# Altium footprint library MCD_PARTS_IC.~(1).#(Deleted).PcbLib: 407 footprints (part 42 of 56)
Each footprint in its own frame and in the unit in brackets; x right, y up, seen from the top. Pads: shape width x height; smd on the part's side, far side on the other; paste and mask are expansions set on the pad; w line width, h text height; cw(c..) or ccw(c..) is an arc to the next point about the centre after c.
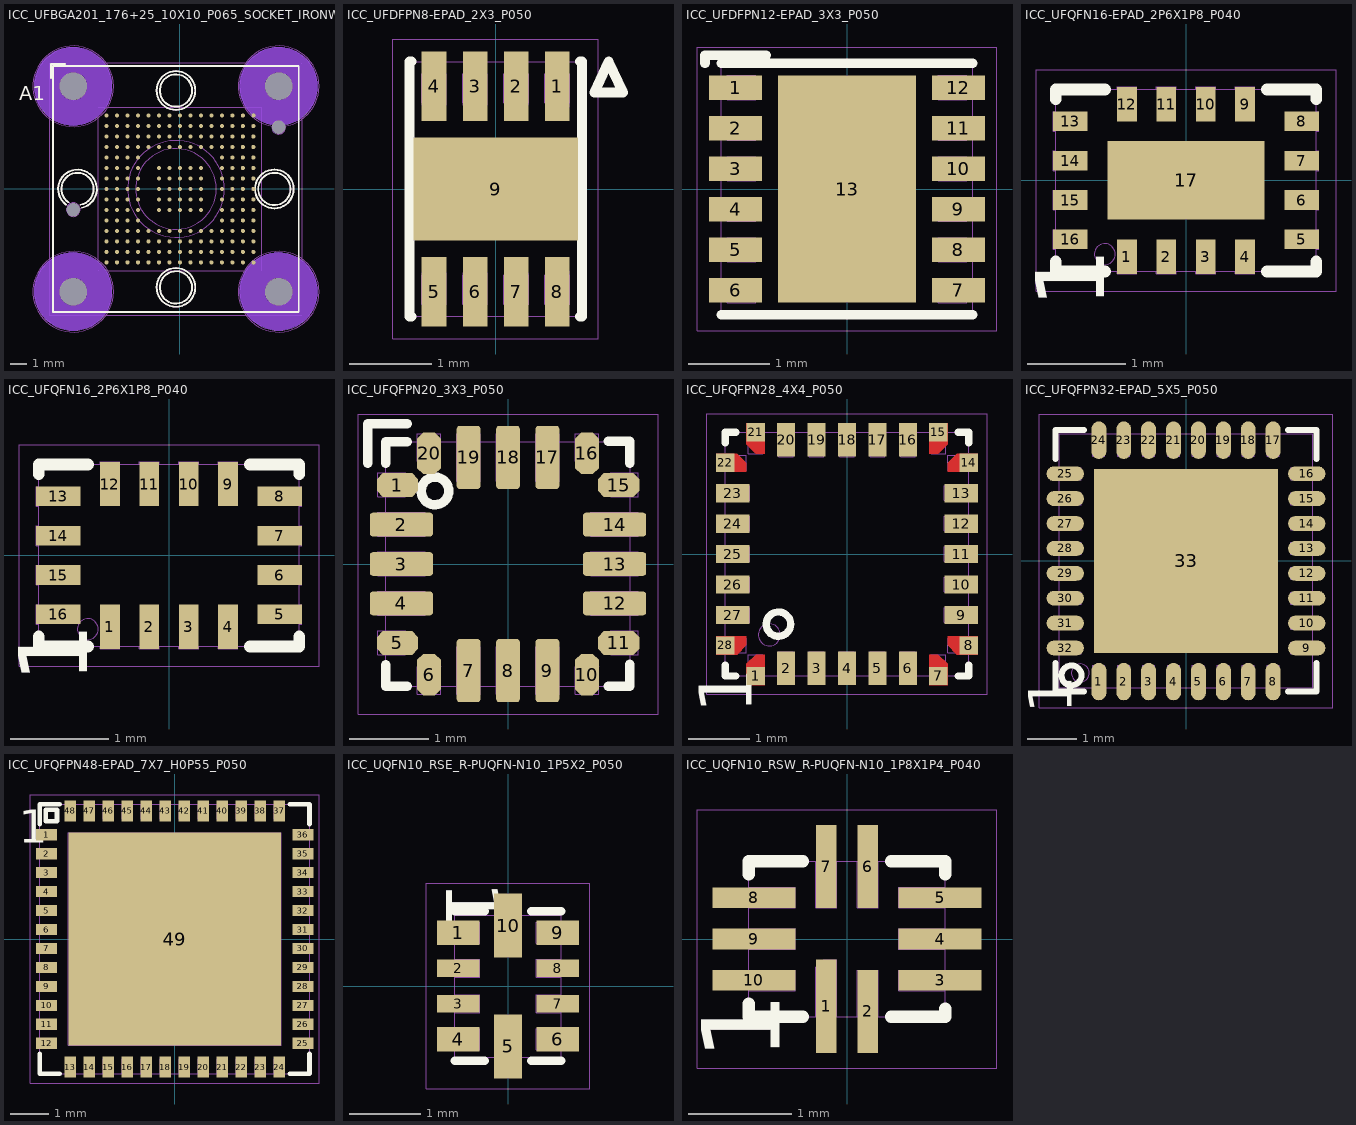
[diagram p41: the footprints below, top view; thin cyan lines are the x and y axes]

## ICC_UFBGA201_176+25_10X10_P065_SOCKET_IRONWOOD_C23913 [mm] "MCD-04409"
height 9.88
pads (207):
  round 0 hole 1.7 unplated mask+0.05: 0(-6.612,-6.368) 0(-6.612,6.362) 0(6.118,-6.368) 0(6.118,6.362)
  round 0 hole 0.85 unplated mask+0.05: 0(-6.612,-1.282) 0(6.118,3.822)
  round 0.25 smd mask+0.038: A1(-4.55,4.55) A2(-3.9,4.55) A3(-3.25,4.55) A4(-2.6,4.55) A5(-1.95,4.55) A6(-1.3,4.55) A7(-0.65,4.55) A8(0,4.55) A9(0.65,4.55) A10(1.3,4.55) A11(1.95,4.55) A12(2.6,4.55) A13(3.25,4.55) A14(3.9,4.55) A15(4.55,4.55) B1(-4.55,3.9) B2(-3.9,3.9) B3(-3.25,3.9) B4(-2.6,3.9) B5(-1.95,3.9) B6(-1.3,3.9) B7(-0.65,3.9) B8(0,3.9) B9(0.65,3.9) B10(1.3,3.9) B11(1.95,3.9) B12(2.6,3.9) B13(3.25,3.9) B14(3.9,3.9) B15(4.55,3.9) C1(-4.55,3.25) C2(-3.9,3.25) C3(-3.25,3.25) C4(-2.6,3.25) C5(-1.95,3.25) C6(-1.3,3.25) C7(-0.65,3.25) C8(0,3.25) C9(0.65,3.25) C10(1.3,3.25) C11(1.95,3.25) C12(2.6,3.25) C13(3.25,3.25) C14(3.9,3.25) C15(4.55,3.25) D1(-4.55,2.6) D2(-3.9,2.6) D3(-3.25,2.6) D4(-2.6,2.6) D5(-1.95,2.6) D6(-1.3,2.6) D7(-0.65,2.6) D8(0,2.6) D9(0.65,2.6) D10(1.3,2.6) D11(1.95,2.6) D12(2.6,2.6) D13(3.25,2.6) D14(3.9,2.6) D15(4.55,2.6) E1(-4.55,1.95) E2(-3.9,1.95) E3(-3.25,1.95) E4(-2.6,1.95) E12(2.6,1.95) E13(3.25,1.95) E14(3.9,1.95) E15(4.55,1.95) F1(-4.55,1.3) F2(-3.9,1.3) F3(-3.25,1.3) F4(-2.6,1.3) F6(-1.3,1.3) F7(-0.65,1.3) F8(0,1.3) F9(0.65,1.3) F10(1.3,1.3) F12(2.6,1.3) F13(3.25,1.3) F14(3.9,1.3) F15(4.55,1.3) G1(-4.55,0.65) G2(-3.9,0.65) G3(-3.25,0.65) G4(-2.6,0.65) G6(-1.3,0.65) G7(-0.65,0.65) G8(0,0.65) G9(0.65,0.65) G10(1.3,0.65) G12(2.6,0.65) G13(3.25,0.65) G14(3.9,0.65) G15(4.55,0.65) H1(-4.55,0) H2(-3.9,0) H3(-3.25,0) H4(-2.6,0) H6(-1.3,0) H7(-0.65,0) H8(0,0) H9(0.65,0) H10(1.3,0) H12(2.6,0) H13(3.25,0) H14(3.9,0) H15(4.55,0) J1(-4.55,-0.65) J2(-3.9,-0.65) J3(-3.25,-0.65) J4(-2.6,-0.65) J6(-1.3,-0.65) J7(-0.65,-0.65) J8(0,-0.65) J9(0.65,-0.65) J10(1.3,-0.65) J12(2.6,-0.65) J13(3.25,-0.65) J14(3.9,-0.65) J15(4.55,-0.65) K1(-4.55,-1.3) K2(-3.9,-1.3) K3(-3.25,-1.3) K4(-2.6,-1.3) K6(-1.3,-1.3) K7(-0.65,-1.3) K8(0,-1.3) K9(0.65,-1.3) K10(1.3,-1.3) K12(2.6,-1.3) K13(3.25,-1.3) K14(3.9,-1.3) K15(4.55,-1.3) L1(-4.55,-1.95) L2(-3.9,-1.95) L3(-3.25,-1.95) L4(-2.6,-1.95) L12(2.6,-1.95) L13(3.25,-1.95) L14(3.9,-1.95) L15(4.55,-1.95) M1(-4.55,-2.6) M2(-3.9,-2.6) M3(-3.25,-2.6) M4(-2.6,-2.6) M5(-1.95,-2.6) M6(-1.3,-2.6) M7(-0.65,-2.6) M8(0,-2.6) M9(0.65,-2.6) M10(1.3,-2.6) M11(1.95,-2.6) M12(2.6,-2.6) M13(3.25,-2.6) M14(3.9,-2.6) M15(4.55,-2.6) N1(-4.55,-3.25) N2(-3.9,-3.25) N3(-3.25,-3.25) N4(-2.6,-3.25) N5(-1.95,-3.25) N6(-1.3,-3.25) N7(-0.65,-3.25) N8(0,-3.25) N9(0.65,-3.25) N10(1.3,-3.25) N11(1.95,-3.25) N12(2.6,-3.25) N13(3.25,-3.25) N14(3.9,-3.25) N15(4.55,-3.25) P1(-4.55,-3.9) P2(-3.9,-3.9) P3(-3.25,-3.9) P4(-2.6,-3.9) P5(-1.95,-3.9) P6(-1.3,-3.9) P7(-0.65,-3.9) P8(0,-3.9) P9(0.65,-3.9) P10(1.3,-3.9) P11(1.95,-3.9) P12(2.6,-3.9) P13(3.25,-3.9) P14(3.9,-3.9) P15(4.55,-3.9) R1(-4.55,-4.55) R2(-3.9,-4.55) R3(-3.25,-4.55) R4(-2.6,-4.55) R5(-1.95,-4.55) R6(-1.3,-4.55) R7(-0.65,-4.55) R8(0,-4.55) R9(0.65,-4.55) R10(1.3,-4.55) R11(1.95,-4.55) R12(2.6,-4.55) R13(3.25,-4.55) R14(3.9,-4.55) R15(4.55,-4.55)
Bottom Layer keep-out:
  region: -4.212,-6.367 -5.75,-6.367 -5.75,-6.355 -5.754,-6.441 -5.788,-6.609 -5.853,-6.767 -5.949,-6.91 -6.07,-7.031 -6.213,-7.127 -6.371,-7.192 -6.539,-7.226 -6.625,-7.23 -6.708,-7.226 -6.872,-7.193 -7.026,-7.13 -7.164,-7.037 -7.282,-6.919 -7.375,-6.781 -7.438,-6.627 -7.471,-6.463 -7.475,-6.38 -7.471,-6.294 -7.437,-6.126 -7.372,-5.968 -7.276,-5.825 -7.155,-5.704 -7.012,-5.608 -6.854,-5.543 -6.686,-5.509 -6.6,-5.505 -6.517,-5.509 -6.353,-5.542 -6.199,-5.605 -6.061,-5.698 -5.943,-5.816 -5.85,-5.954 -5.787,-6.108 -5.754,-6.272 -5.75,-6.355 -4.212,-6.367 -4.212,-6.13 -4.305,-5.664 -4.487,-5.225 -4.751,-4.83 -5.087,-4.494 -5.482,-4.23 -5.921,-4.048 -6.387,-3.955 -6.625,-3.955 -6.65,-3.955 -6.884,-3.955 -7.343,-4.046 -7.775,-4.225 -8.164,-4.485 -8.495,-4.816 -8.755,-5.205 -8.934,-5.637 -9.025,-6.096 -9.025,-6.33 -9.025,-6.355 -9.025,-6.593 -8.932,-7.059 -8.75,-7.498 -8.486,-7.893 -8.15,-8.229 -7.755,-8.493 -7.316,-8.675 -6.85,-8.767 -6.613,-8.767 -6.612,-8.767 -6.375,-8.767 -5.912,-8.675 -5.475,-8.494 -5.082,-8.232 -4.748,-7.898 -4.485,-7.505 -4.305,-7.068 -4.212,-6.605 -4.212,-6.368
  region: 8.513,-6.362 6.975,-6.362 6.975,-6.35 6.971,-6.436 6.937,-6.604 6.872,-6.762 6.776,-6.905 6.655,-7.026 6.513,-7.122 6.354,-7.187 6.186,-7.221 6.1,-7.225 6.017,-7.221 5.853,-7.188 5.699,-7.125 5.561,-7.032 5.443,-6.914 5.35,-6.776 5.287,-6.622 5.254,-6.458 5.25,-6.375 5.254,-6.289 5.288,-6.121 5.353,-5.962 5.449,-5.82 5.57,-5.699 5.713,-5.603 5.871,-5.538 6.039,-5.504 6.125,-5.5 6.208,-5.504 6.372,-5.537 6.526,-5.6 6.664,-5.693 6.782,-5.811 6.875,-5.949 6.938,-6.103 6.971,-6.267 6.975,-6.35 8.513,-6.362 8.513,-6.125 8.42,-5.659 8.238,-5.22 7.974,-4.825 7.638,-4.488 7.243,-4.224 6.804,-4.043 6.338,-3.95 6.1,-3.95 6.075,-3.95 5.841,-3.95 5.382,-4.041 4.95,-4.22 4.561,-4.48 4.23,-4.811 3.97,-5.2 3.791,-5.632 3.7,-6.091 3.7,-6.325 3.7,-6.35 3.7,-6.588 3.793,-7.054 3.975,-7.493 4.239,-7.888 4.575,-8.224 4.97,-8.488 5.409,-8.67 5.875,-8.762 6.112,-8.762 6.113,-8.762 6.35,-8.762 6.813,-8.67 7.25,-8.489 7.643,-8.227 7.977,-7.893 8.24,-7.5 8.42,-7.063 8.513,-6.599 8.513,-6.363
  region: 8.518,6.363 6.98,6.363 6.98,6.375 6.976,6.289 6.942,6.121 6.877,5.963 6.781,5.82 6.66,5.699 6.517,5.603 6.359,5.538 6.191,5.504 6.105,5.5 6.022,5.504 5.858,5.537 5.704,5.6 5.566,5.693 5.448,5.811 5.355,5.949 5.292,6.103 5.259,6.267 5.255,6.35 5.259,6.436 5.293,6.604 5.358,6.762 5.454,6.905 5.575,7.026 5.718,7.122 5.876,7.187 6.044,7.221 6.13,7.225 6.213,7.221 6.377,7.188 6.531,7.125 6.669,7.032 6.787,6.914 6.88,6.776 6.943,6.622 6.976,6.458 6.98,6.375 8.518,6.363 8.518,6.6 8.425,7.066 8.243,7.505 7.979,7.9 7.643,8.236 7.248,8.5 6.809,8.682 6.343,8.775 6.105,8.775 6.08,8.775 5.846,8.775 5.387,8.684 4.955,8.505 4.566,8.245 4.235,7.914 3.975,7.525 3.796,7.093 3.705,6.634 3.705,6.4 3.705,6.375 3.705,6.137 3.798,5.671 3.98,5.232 4.244,4.837 4.58,4.501 4.975,4.237 5.414,4.055 5.88,3.963 6.117,3.963 6.118,3.963 6.355,3.963 6.818,4.055 7.255,4.236 7.648,4.498 7.982,4.832 8.245,5.225 8.425,5.662 8.518,6.125 8.518,6.362
  region: -4.212,6.363 -5.75,6.363 -5.75,6.375 -5.754,6.289 -5.788,6.121 -5.853,5.963 -5.949,5.82 -6.07,5.699 -6.213,5.603 -6.371,5.538 -6.539,5.504 -6.625,5.5 -6.708,5.504 -6.872,5.537 -7.026,5.6 -7.164,5.693 -7.282,5.811 -7.375,5.949 -7.438,6.103 -7.471,6.267 -7.475,6.35 -7.471,6.436 -7.437,6.604 -7.372,6.762 -7.276,6.905 -7.155,7.026 -7.012,7.122 -6.854,7.187 -6.686,7.221 -6.6,7.225 -6.517,7.221 -6.353,7.188 -6.199,7.125 -6.061,7.032 -5.943,6.914 -5.85,6.776 -5.787,6.622 -5.754,6.458 -5.75,6.375 -4.212,6.363 -4.212,6.6 -4.305,7.066 -4.487,7.505 -4.751,7.9 -5.087,8.236 -5.482,8.5 -5.921,8.682 -6.387,8.775 -6.625,8.775 -6.65,8.775 -6.884,8.775 -7.343,8.684 -7.775,8.505 -8.164,8.245 -8.495,7.914 -8.755,7.525 -8.934,7.093 -9.025,6.634 -9.025,6.4 -9.025,6.375 -9.025,6.137 -8.932,5.671 -8.75,5.232 -8.486,4.837 -8.15,4.501 -7.755,4.237 -7.316,4.055 -6.85,3.963 -6.613,3.963 -6.612,3.963 -6.375,3.963 -5.912,4.055 -5.475,4.236 -5.082,4.498 -4.748,4.832 -4.485,5.225 -4.305,5.662 -4.212,6.125 -4.212,6.362
Top Overlay:
  circle w0.12: c-0.25,-6.1 r1.2
  circle w0.12: c-0.25,-6.1 r1
  circle w0.12: c-0.25,6.1 r1.2
  circle w0.12: c-0.25,6.1 r1
  circle w0.12: c5.85,0 r1
  circle w0.12: c5.85,0 r1.2
  lines w0.12: -8,6.875 -8,7.75 -7.125,7.75 ; -7.066,-0.963 cw(c-6.35,0) -6.059,-1.164 ; -6.918,-0.823 cw(c-6.35,0) -6.154,-0.98 ; -7.862,-7.612 -7.862,7.613 7.363,7.613 7.363,-7.612 -7.862,-7.612
  text "A1" at -9.975,5.175 h1.5
Bottom Overlay:
  circle w0.12: c-6.612,6.363 r2.4
  circle w0.12: c6.113,6.363 r2.4
  circle w0.12: c6.113,-6.362 r2.4
  circle w0.12: c-6.612,-6.362 r2.4
M14-Top Assembly:
  circle w0.01: c-0.25,0 r3
  circle w0.01: c-0.25,0 r2.5
  circle w0.01: c5.85,0 r1.2
  circle w0.01: c5.85,0 r1
  circle w0.01: c-0.25,6.1 r1
  circle w0.01: c-0.25,6.1 r1.2
  circle w0.01: c-6.35,0 r1
  circle w0.01: c-6.35,0 r1.2
  circle w0.01: c-0.25,-6.1 r1
  circle w0.01: c-0.25,-6.1 r1.2
  lines w0.01: -7.862,-7.612 7.363,-7.612 7.363,7.613 -7.862,7.613 -7.862,-7.612 ; -5.075,-5.075 5.075,-5.075 5.075,5.075 -5.075,5.075 -5.075,-5.075
  text "A1" at -4.9,4.4 h0.75
  text "'.Designator'" at -2,-0.5 h0.75
M15-Bottom Assembly:
  circle w0.01: c6.118,6.362 r2.4
  circle w0.01: c6.118,-6.368 r2.4
  circle w0.01: c-6.612,-6.368 r2.4
  circle w0.01: c-6.612,6.362 r2.4
  circle w0.01: c6.118,3.822 r0.425
  circle w0.01: c-6.612,-1.282 r0.425
  circle w0.01: c6.118,-6.368 r0.85
  circle w0.01: c-6.612,-6.368 r0.85
  circle w0.01: c6.118,6.362 r0.85
  circle w0.01: c-6.612,6.362 r0.85
M16-Top Courtyard:
  lines w0.01: -8.075,-7.825 -8.075,7.825 7.575,7.825 7.575,-7.825 -8.075,-7.825
M17-Bottom Courtyard:
  circle w0.01: c6.118,6.362 r2.5
  circle w0.01: c6.118,-6.368 r2.5
  circle w0.01: c-6.612,-6.368 r2.5
  circle w0.01: c-6.612,6.363 r2.5
3D body: height 9.88, standoff 0.6, extent -0.25,-3 2.75,3
3D body: height 9.88, standoff 0.6, extent -3.25,-3 -0.25,3
3D body: height 9.88, standoff 7, extent -0.25,-7.3 0.95,-4.9
3D body: height 9.88, standoff 7, extent -1.45,-7.3 -0.25,-4.9
3D body: height 9.88, standoff 7, extent 5.85,-1.2 7.05,1.2
3D body: height 9.88, standoff 7, extent 4.65,-1.2 5.85,1.2
3D body: height 9.88, standoff 7, extent -0.25,4.9 0.95,7.3
3D body: height 9.88, standoff 7, extent -1.45,4.9 -0.25,7.3
3D body: height 9.88, standoff 7, extent -7.55,-1.2 -6.35,1.2
3D body: height 9.88, standoff 7, extent -6.35,-1.2 -5.15,1.2
3D body: height 7.1, standoff 3, extent -1.242,-7.098 0.75,-5.102
3D body: height 7.1, standoff 3, extent 4.858,-0.998 6.85,0.998
3D body: height 7.1, standoff 3, extent -1.242,5.102 0.75,7.098
3D body: height 7.1, standoff 3, extent -7.342,-0.998 -5.35,0.998
3D body: height 0.6, standoff 0, extent -7.862,-7.612 7.363,7.613
3D body: height 1.5, standoff 0.6, extent -7.862,-7.612 7.363,7.613
3D body: height 3, standoff 1.5, extent -7.862,-7.612 7.363,7.613
3D body: height 4.5, standoff 3, extent -7.803,5.165 -5.412,7.56
3D body: height 4.5, standoff 3, extent 4.922,5.165 7.313,7.56
3D body: height 4.5, standoff 3, extent 4.922,-7.56 7.313,-5.165
3D body: height 4.5, standoff 3, extent -7.803,-7.56 -5.412,-5.165
3D body: height 7, standoff 4.5, extent -7.862,-7.612 -0.25,7.613
3D body: height 7, standoff 4.5, extent -0.25,-7.612 7.363,7.613
3D body: height 7.1, standoff 0.6, extent -2.75,-2.497 2.25,2.497
3D body: height 0.61, standoff 0.6, extent -4.798,4.301 -4.3,4.8
3D body: height 0.6, standoff 0.15, extent -5.075,-5.075 5.075,5.075
3D body: height 0.25, standoff -0.05, extent -4.036,4.407 -3.755,4.693
3D body: height 0.25, standoff -0.05, extent -4.686,4.407 -4.405,4.693
3D body: height 0.25, standoff -0.05, extent -3.386,4.407 -3.105,4.693
3D body: height 0.25, standoff -0.05, extent -2.736,4.407 -2.455,4.693
3D body: height 0.25, standoff -0.05, extent -2.086,4.407 -1.805,4.693
3D body: height 0.25, standoff -0.05, extent -1.436,4.407 -1.155,4.693
3D body: height 0.25, standoff -0.05, extent -0.786,4.407 -0.505,4.693
3D body: height 0.25, standoff -0.05, extent -0.136,4.407 0.145,4.693
3D body: height 0.25, standoff -0.05, extent 0.514,4.407 0.795,4.693
3D body: height 0.25, standoff -0.05, extent 1.164,4.407 1.445,4.693
3D body: height 0.25, standoff -0.05, extent 1.814,4.407 2.095,4.693
3D body: height 0.25, standoff -0.05, extent 2.464,4.407 2.745,4.693
3D body: height 0.25, standoff -0.05, extent 3.114,4.407 3.395,4.693
3D body: height 0.25, standoff -0.05, extent 3.764,4.407 4.045,4.693
3D body: height 0.25, standoff -0.05, extent 4.414,4.407 4.695,4.693
3D body: height 0.25, standoff -0.05, extent 4.414,3.757 4.695,4.043
3D body: height 0.25, standoff -0.05, extent 3.764,3.757 4.045,4.043
3D body: height 0.25, standoff -0.05, extent 3.114,3.757 3.395,4.043
3D body: height 0.25, standoff -0.05, extent 2.464,3.757 2.745,4.043
3D body: height 0.25, standoff -0.05, extent 1.814,3.757 2.095,4.043
3D body: height 0.25, standoff -0.05, extent 1.164,3.757 1.445,4.043
3D body: height 0.25, standoff -0.05, extent 0.514,3.757 0.795,4.043
3D body: height 0.25, standoff -0.05, extent -0.136,3.757 0.145,4.043
3D body: height 0.25, standoff -0.05, extent -0.786,3.757 -0.505,4.043
3D body: height 0.25, standoff -0.05, extent -1.436,3.757 -1.155,4.043
3D body: height 0.25, standoff -0.05, extent -2.086,3.757 -1.805,4.043
3D body: height 0.25, standoff -0.05, extent -2.736,3.757 -2.455,4.043
3D body: height 0.25, standoff -0.05, extent -3.386,3.757 -3.105,4.043
3D body: height 0.25, standoff -0.05, extent -4.686,3.757 -4.405,4.043
3D body: height 0.25, standoff -0.05, extent -4.036,3.757 -3.755,4.043
3D body: height 0.25, standoff -0.05, extent 4.414,3.107 4.695,3.393
3D body: height 0.25, standoff -0.05, extent 3.764,3.107 4.045,3.393
3D body: height 0.25, standoff -0.05, extent 3.114,3.107 3.395,3.393
3D body: height 0.25, standoff -0.05, extent 2.464,3.107 2.745,3.393
3D body: height 0.25, standoff -0.05, extent 1.814,3.107 2.095,3.393
3D body: height 0.25, standoff -0.05, extent 1.164,3.107 1.445,3.393
3D body: height 0.25, standoff -0.05, extent 0.514,3.107 0.795,3.393
3D body: height 0.25, standoff -0.05, extent -0.136,3.107 0.145,3.393
3D body: height 0.25, standoff -0.05, extent -0.786,3.107 -0.505,3.393
3D body: height 0.25, standoff -0.05, extent -1.436,3.107 -1.155,3.393
3D body: height 0.25, standoff -0.05, extent -2.086,3.107 -1.805,3.393
3D body: height 0.25, standoff -0.05, extent -2.736,3.107 -2.455,3.393
3D body: height 0.25, standoff -0.05, extent -3.386,3.107 -3.105,3.393
3D body: height 0.25, standoff -0.05, extent -4.686,3.107 -4.405,3.393
3D body: height 0.25, standoff -0.05, extent -4.036,3.107 -3.755,3.393
3D body: height 0.25, standoff -0.05, extent 4.414,2.457 4.695,2.743
3D body: height 0.25, standoff -0.05, extent 3.764,2.457 4.045,2.743
3D body: height 0.25, standoff -0.05, extent 3.114,2.457 3.395,2.743
3D body: height 0.25, standoff -0.05, extent 2.464,2.457 2.745,2.743
3D body: height 0.25, standoff -0.05, extent 1.814,2.457 2.095,2.743
3D body: height 0.25, standoff -0.05, extent 1.164,2.457 1.445,2.743
3D body: height 0.25, standoff -0.05, extent 0.514,2.457 0.795,2.743
3D body: height 0.25, standoff -0.05, extent -0.136,2.457 0.145,2.743
3D body: height 0.25, standoff -0.05, extent -0.786,2.457 -0.505,2.743
3D body: height 0.25, standoff -0.05, extent -1.436,2.457 -1.155,2.743
3D body: height 0.25, standoff -0.05, extent -2.086,2.457 -1.805,2.743
3D body: height 0.25, standoff -0.05, extent -2.736,2.457 -2.455,2.743
3D body: height 0.25, standoff -0.05, extent -3.386,2.457 -3.105,2.743
3D body: height 0.25, standoff -0.05, extent -4.686,2.457 -4.405,2.743
3D body: height 0.25, standoff -0.05, extent -4.036,2.457 -3.755,2.743
3D body: height 0.25, standoff -0.05, extent 4.414,1.807 4.695,2.093
3D body: height 0.25, standoff -0.05, extent 3.764,1.807 4.045,2.093
3D body: height 0.25, standoff -0.05, extent 3.114,1.807 3.395,2.093
3D body: height 0.25, standoff -0.05, extent 2.464,1.807 2.745,2.093
3D body: height 0.25, standoff -0.05, extent -2.736,1.807 -2.455,2.093
3D body: height 0.25, standoff -0.05, extent -3.386,1.807 -3.105,2.093
3D body: height 0.25, standoff -0.05, extent -4.686,1.807 -4.405,2.093
3D body: height 0.25, standoff -0.05, extent -4.036,1.807 -3.755,2.093
3D body: height 0.25, standoff -0.05, extent -4.036,-1.443 -3.755,-1.157
3D body: height 0.25, standoff -0.05, extent -4.686,-1.443 -4.405,-1.157
3D body: height 0.25, standoff -0.05, extent -3.386,-1.443 -3.105,-1.157
3D body: height 0.25, standoff -0.05, extent -2.736,-1.443 -2.455,-1.157
3D body: height 0.25, standoff -0.05, extent -1.436,-1.443 -1.155,-1.157
3D body: height 0.25, standoff -0.05, extent -0.786,-1.443 -0.505,-1.157
3D body: height 0.25, standoff -0.05, extent -0.136,-1.443 0.145,-1.157
3D body: height 0.25, standoff -0.05, extent 0.514,-1.443 0.795,-1.157
3D body: height 0.25, standoff -0.05, extent 1.164,-1.443 1.445,-1.157
3D body: height 0.25, standoff -0.05, extent 2.464,-1.443 2.745,-1.157
3D body: height 0.25, standoff -0.05, extent 3.114,-1.443 3.395,-1.157
3D body: height 0.25, standoff -0.05, extent 3.764,-1.443 4.045,-1.157
3D body: height 0.25, standoff -0.05, extent 4.414,-1.443 4.695,-1.157
3D body: height 0.25, standoff -0.05, extent -4.036,-0.793 -3.755,-0.507
3D body: height 0.25, standoff -0.05, extent -4.686,-0.793 -4.405,-0.507
3D body: height 0.25, standoff -0.05, extent -3.386,-0.793 -3.105,-0.507
3D body: height 0.25, standoff -0.05, extent -2.736,-0.793 -2.455,-0.507
3D body: height 0.25, standoff -0.05, extent -1.436,-0.793 -1.155,-0.507
3D body: height 0.25, standoff -0.05, extent -0.786,-0.793 -0.505,-0.507
3D body: height 0.25, standoff -0.05, extent -0.136,-0.793 0.145,-0.507
3D body: height 0.25, standoff -0.05, extent 0.514,-0.793 0.795,-0.507
3D body: height 0.25, standoff -0.05, extent 1.164,-0.793 1.445,-0.507
3D body: height 0.25, standoff -0.05, extent 2.464,-0.793 2.745,-0.507
3D body: height 0.25, standoff -0.05, extent 3.114,-0.793 3.395,-0.507
3D body: height 0.25, standoff -0.05, extent 3.764,-0.793 4.045,-0.507
3D body: height 0.25, standoff -0.05, extent 4.414,-0.793 4.695,-0.507
3D body: height 0.25, standoff -0.05, extent -4.036,-0.143 -3.755,0.143
3D body: height 0.25, standoff -0.05, extent -4.686,-0.143 -4.405,0.143
3D body: height 0.25, standoff -0.05, extent -3.386,-0.143 -3.105,0.143
3D body: height 0.25, standoff -0.05, extent -2.736,-0.143 -2.455,0.143
3D body: height 0.25, standoff -0.05, extent -1.436,-0.143 -1.155,0.143
3D body: height 0.25, standoff -0.05, extent -0.786,-0.143 -0.505,0.143
3D body: height 0.25, standoff -0.05, extent -0.136,-0.143 0.145,0.143
3D body: height 0.25, standoff -0.05, extent 0.514,-0.143 0.795,0.143
3D body: height 0.25, standoff -0.05, extent 1.164,-0.143 1.445,0.143
3D body: height 0.25, standoff -0.05, extent 2.464,-0.143 2.745,0.143
3D body: height 0.25, standoff -0.05, extent 3.114,-0.143 3.395,0.143
3D body: height 0.25, standoff -0.05, extent 3.764,-0.143 4.045,0.143
3D body: height 0.25, standoff -0.05, extent 4.414,-0.143 4.695,0.143
3D body: height 0.25, standoff -0.05, extent -4.036,0.507 -3.755,0.793
3D body: height 0.25, standoff -0.05, extent -4.686,0.507 -4.405,0.793
3D body: height 0.25, standoff -0.05, extent -3.386,0.507 -3.105,0.793
3D body: height 0.25, standoff -0.05, extent -2.736,0.507 -2.455,0.793
3D body: height 0.25, standoff -0.05, extent -1.436,0.507 -1.155,0.793
3D body: height 0.25, standoff -0.05, extent -0.786,0.507 -0.505,0.793
3D body: height 0.25, standoff -0.05, extent -0.136,0.507 0.145,0.793
3D body: height 0.25, standoff -0.05, extent 0.514,0.507 0.795,0.793
3D body: height 0.25, standoff -0.05, extent 1.164,0.507 1.445,0.793
3D body: height 0.25, standoff -0.05, extent 2.464,0.507 2.745,0.793
3D body: height 0.25, standoff -0.05, extent 3.114,0.507 3.395,0.793
3D body: height 0.25, standoff -0.05, extent 3.764,0.507 4.045,0.793
3D body: height 0.25, standoff -0.05, extent 4.414,0.507 4.695,0.793
3D body: height 0.25, standoff -0.05, extent 4.414,1.157 4.695,1.443
3D body: height 0.25, standoff -0.05, extent 3.764,1.157 4.045,1.443
3D body: height 0.25, standoff -0.05, extent 3.114,1.157 3.395,1.443
3D body: height 0.25, standoff -0.05, extent 2.464,1.157 2.745,1.443
3D body: height 0.25, standoff -0.05, extent 1.164,1.157 1.445,1.443
3D body: height 0.25, standoff -0.05, extent 0.514,1.157 0.795,1.443
3D body: height 0.25, standoff -0.05, extent -0.136,1.157 0.145,1.443
3D body: height 0.25, standoff -0.05, extent -0.786,1.157 -0.505,1.443
3D body: height 0.25, standoff -0.05, extent -1.436,1.157 -1.155,1.443
3D body: height 0.25, standoff -0.05, extent -2.736,1.157 -2.455,1.443
3D body: height 0.25, standoff -0.05, extent -3.386,1.157 -3.105,1.443
3D body: height 0.25, standoff -0.05, extent -4.686,1.157 -4.405,1.443
3D body: height 0.25, standoff -0.05, extent -4.036,1.157 -3.755,1.443
3D body: height 0.25, standoff -0.05, extent -4.036,-4.693 -3.755,-4.407
3D body: height 0.25, standoff -0.05, extent -4.686,-4.693 -4.405,-4.407
3D body: height 0.25, standoff -0.05, extent -3.386,-4.693 -3.105,-4.407
3D body: height 0.25, standoff -0.05, extent -2.736,-4.693 -2.455,-4.407
3D body: height 0.25, standoff -0.05, extent -2.086,-4.693 -1.805,-4.407
3D body: height 0.25, standoff -0.05, extent -1.436,-4.693 -1.155,-4.407
3D body: height 0.25, standoff -0.05, extent -0.786,-4.693 -0.505,-4.407
3D body: height 0.25, standoff -0.05, extent -0.136,-4.693 0.145,-4.407
3D body: height 0.25, standoff -0.05, extent 0.514,-4.693 0.795,-4.407
3D body: height 0.25, standoff -0.05, extent 1.164,-4.693 1.445,-4.407
3D body: height 0.25, standoff -0.05, extent 1.814,-4.693 2.095,-4.407
3D body: height 0.25, standoff -0.05, extent 2.464,-4.693 2.745,-4.407
3D body: height 0.25, standoff -0.05, extent 3.114,-4.693 3.395,-4.407
3D body: height 0.25, standoff -0.05, extent 3.764,-4.693 4.045,-4.407
3D body: height 0.25, standoff -0.05, extent 4.414,-4.693 4.695,-4.407
3D body: height 0.25, standoff -0.05, extent -4.036,-4.043 -3.755,-3.757
3D body: height 0.25, standoff -0.05, extent -4.686,-4.043 -4.405,-3.757
3D body: height 0.25, standoff -0.05, extent -3.386,-4.043 -3.105,-3.757
3D body: height 0.25, standoff -0.05, extent -2.736,-4.043 -2.455,-3.757
3D body: height 0.25, standoff -0.05, extent -2.086,-4.043 -1.805,-3.757
3D body: height 0.25, standoff -0.05, extent -1.436,-4.043 -1.155,-3.757
3D body: height 0.25, standoff -0.05, extent -0.786,-4.043 -0.505,-3.757
3D body: height 0.25, standoff -0.05, extent -0.136,-4.043 0.145,-3.757
3D body: height 0.25, standoff -0.05, extent 0.514,-4.043 0.795,-3.757
3D body: height 0.25, standoff -0.05, extent 1.164,-4.043 1.445,-3.757
3D body: height 0.25, standoff -0.05, extent 1.814,-4.043 2.095,-3.757
3D body: height 0.25, standoff -0.05, extent 2.464,-4.043 2.745,-3.757
3D body: height 0.25, standoff -0.05, extent 3.114,-4.043 3.395,-3.757
3D body: height 0.25, standoff -0.05, extent 3.764,-4.043 4.045,-3.757
3D body: height 0.25, standoff -0.05, extent 4.414,-4.043 4.695,-3.757
3D body: height 0.25, standoff -0.05, extent -4.036,-3.393 -3.755,-3.107
3D body: height 0.25, standoff -0.05, extent -4.686,-3.393 -4.405,-3.107
3D body: height 0.25, standoff -0.05, extent -3.386,-3.393 -3.105,-3.107
3D body: height 0.25, standoff -0.05, extent -2.736,-3.393 -2.455,-3.107
3D body: height 0.25, standoff -0.05, extent -2.086,-3.393 -1.805,-3.107
3D body: height 0.25, standoff -0.05, extent -1.436,-3.393 -1.155,-3.107
3D body: height 0.25, standoff -0.05, extent -0.786,-3.393 -0.505,-3.107
3D body: height 0.25, standoff -0.05, extent -0.136,-3.393 0.145,-3.107
3D body: height 0.25, standoff -0.05, extent 0.514,-3.393 0.795,-3.107
3D body: height 0.25, standoff -0.05, extent 1.164,-3.393 1.445,-3.107
3D body: height 0.25, standoff -0.05, extent 1.814,-3.393 2.095,-3.107
3D body: height 0.25, standoff -0.05, extent 2.464,-3.393 2.745,-3.107
3D body: height 0.25, standoff -0.05, extent 3.114,-3.393 3.395,-3.107
3D body: height 0.25, standoff -0.05, extent 3.764,-3.393 4.045,-3.107
3D body: height 0.25, standoff -0.05, extent 4.414,-3.393 4.695,-3.107
3D body: height 0.25, standoff -0.05, extent -4.036,-2.743 -3.755,-2.457
3D body: height 0.25, standoff -0.05, extent -4.686,-2.743 -4.405,-2.457
3D body: height 0.25, standoff -0.05, extent -3.386,-2.743 -3.105,-2.457
3D body: height 0.25, standoff -0.05, extent -2.736,-2.743 -2.455,-2.457
3D body: height 0.25, standoff -0.05, extent -2.086,-2.743 -1.805,-2.457
3D body: height 0.25, standoff -0.05, extent -1.436,-2.743 -1.155,-2.457
3D body: height 0.25, standoff -0.05, extent -0.786,-2.743 -0.505,-2.457
3D body: height 0.25, standoff -0.05, extent -0.136,-2.743 0.145,-2.457
3D body: height 0.25, standoff -0.05, extent 0.514,-2.743 0.795,-2.457
3D body: height 0.25, standoff -0.05, extent 1.164,-2.743 1.445,-2.457
3D body: height 0.25, standoff -0.05, extent 1.814,-2.743 2.095,-2.457
3D body: height 0.25, standoff -0.05, extent 2.464,-2.743 2.745,-2.457
3D body: height 0.25, standoff -0.05, extent 3.114,-2.743 3.395,-2.457
3D body: height 0.25, standoff -0.05, extent 3.764,-2.743 4.045,-2.457
3D body: height 0.25, standoff -0.05, extent 4.414,-2.743 4.695,-2.457
3D body: height 0.25, standoff -0.05, extent 4.414,-2.093 4.695,-1.807
3D body: height 0.25, standoff -0.05, extent 3.764,-2.093 4.045,-1.807
3D body: height 0.25, standoff -0.05, extent 3.114,-2.093 3.395,-1.807
3D body: height 0.25, standoff -0.05, extent 2.464,-2.093 2.745,-1.807
3D body: height 0.25, standoff -0.05, extent -2.736,-2.093 -2.455,-1.807
3D body: height 0.25, standoff -0.05, extent -3.386,-2.093 -3.105,-1.807
3D body: height 0.25, standoff -0.05, extent -4.686,-2.093 -4.405,-1.807
3D body: height 0.25, standoff -0.05, extent -4.036,-2.093 -3.755,-1.807
3D body: height 4, standoff 0, extent -9.012,-8.762 -4.212,-3.962
3D body: height 4, standoff 0, extent 3.713,-8.762 8.513,-3.962
3D body: height 4, standoff 0, extent 3.713,3.963 8.513,8.763
3D body: height 4, standoff 0, extent -9.012,3.963 -4.212,8.763

## ICC_UFDFPN8-EPAD_2X3_P050 [mm] "MCD-01436"
height 0.6
pads (9):
  rect 0.3x0.85 smd mask+0.05: 1(0.75,1.25) 2(0.25,1.25) 3(-0.25,1.25) 4(-0.75,1.25) 5(-0.75,-1.25) 6(-0.25,-1.25) 7(0.25,-1.25) 8(0.75,-1.25)
  rect 2x1.25 smd mask+0.05: 9(0,0)
Top Overlay:
  lines w0.12: -1.025,-1.55 -1.05,-1.55 -1.05,1.55 -1.025,1.55 ; 1.025,-1.55 1.05,-1.55 1.05,1.55 1.025,1.55 ; 1.2,1.175 1.375,1.55 1.55,1.175 1.2,1.175
M14-Top Assembly:
  lines w0.01: -1.05,-1.55 1.05,-1.55 1.05,1.55 -1.05,1.55 -1.05,-1.55 ; -0.9,-1.4 -0.6,-1.4 -0.6,-1.05 ccw(c-0.75,-1.05) -0.75,-0.9 ccw(c-0.75,-1.05) -0.9,-1.05 -0.9,-1.4 ; -0.9,1.05 ccw(c-0.75,1.05) -0.75,0.9 ccw(c-0.75,1.05) -0.6,1.05 -0.6,1.4 -0.9,1.4 -0.9,1.05 ; -0.85,-0.15 0.85,-0.15 0.85,0.15 -0.85,0.15 -0.85,-0.15 ; -0.4,-1.4 -0.4,-1.05 cw(c-0.25,-1.05) -0.25,-0.9 cw(c-0.25,-1.05) -0.1,-1.05 -0.1,-1.4 -0.4,-1.4 ; -0.4,1.05 ccw(c-0.25,1.05) -0.25,0.9 ccw(c-0.25,1.05) -0.1,1.05 -0.1,1.4 -0.4,1.4 -0.4,1.05 ; 0.1,-1.4 0.1,-1.05 cw(c0.25,-1.05) 0.25,-0.9 cw(c0.25,-1.05) 0.4,-1.05 0.4,-1.4 0.1,-1.4 ; 0.1,1.05 ccw(c0.25,1.05) 0.25,0.9 ccw(c0.25,1.05) 0.4,1.05 0.4,1.4 0.1,1.4 0.1,1.05 ; 0.6,-1.4 0.6,-1.05 cw(c0.75,-1.05) 0.75,-0.9 cw(c0.75,-1.05) 0.9,-1.05 0.9,-1.4 0.6,-1.4 ; 0.6,1.05 ccw(c0.75,1.05) 0.75,0.9 ccw(c0.75,1.05) 0.9,1.05 0.9,1.4 0.6,1.4 0.6,1.05
  text "'.Designator'" at -2,0.05 h0.75
  text "1" at 0.675,1.025 h0.5
  text "4" at -0.875,1.025 h0.5
  text "9" at -0.1,-0.125 h0.4
  text "5" at -0.85,-1.35 h0.5
  text "8" at 0.65,-1.35 h0.5
M16-Top Courtyard:
  lines w0.01: -1.25,-1.825 -1.25,1.825 1.25,1.825 1.25,-1.825 -1.25,-1.825
3D body: height 0.6, standoff 0, extent -1.05,-1.55 1.05,1.55
3D body "UFDFPN8.STEP": height 0.55, standoff 0, extent -1,-1.5 1,1.5

## ICC_UFDFPN12-EPAD_3X3_P050 [mm] "MCD-03766"
height 0.6
pads (13):
  rect 0.65x0.3 smd mask+0.05: 1(-1.375,1.25) 2(-1.375,0.75) 3(-1.375,0.25) 4(-1.375,-0.25) 5(-1.375,-0.75) 6(-1.375,-1.25) 7(1.375,-1.25) 8(1.375,-0.75) 9(1.375,-0.25) 10(1.375,0.25) 11(1.375,0.75) 12(1.375,1.25)
  rect 1.7x2.8 smd mask+0.05: 13(0,0)
Top Overlay:
  lines w0.12: -1.75,1.55 -1.75,1.65 -1,1.65 ; -1.55,-1.55 1.55,-1.55 ; -1.55,1.55 1.55,1.55
M14-Top Assembly:
  lines w0.01: -1.55,-1.55 -1.55,1.55 1.55,1.55 1.55,-1.55 -1.55,-1.55 ; -1.475,-1.4 -1.475,-1.1 -1.125,-1.1 -1.125,-1.4 -1.475,-1.4 ; -1.475,-0.9 -1.475,-0.6 -1.125,-0.6 -1.125,-0.9 -1.475,-0.9 ; -1.475,-0.4 -1.475,-0.1 -1.125,-0.1 -1.125,-0.4 -1.475,-0.4 ; -1.475,0.1 -1.475,0.4 -1.125,0.4 -1.125,0.1 -1.475,0.1 ; -1.475,0.6 -1.475,0.9 -1.125,0.9 -1.125,0.6 -1.475,0.6 ; -1.475,1.1 -1.475,1.4 -1.125,1.4 -1.125,1.1 -1.475,1.1 ; -0.725,-1.3 -0.725,1.3 0.725,1.3 0.725,-1.3 -0.725,-1.3 ; 1.125,-1.4 1.125,-1.1 1.475,-1.1 1.475,-1.4 1.125,-1.4 ; 1.125,-0.9 1.125,-0.6 1.475,-0.6 1.475,-0.9 1.125,-0.9 ; 1.125,-0.4 1.125,-0.1 1.475,-0.1 1.475,-0.4 1.125,-0.4 ; 1.125,0.1 1.125,0.4 1.475,0.4 1.475,0.1 1.125,0.1 ; 1.125,0.6 1.125,0.9 1.475,0.9 1.475,0.6 1.125,0.6 ; 1.125,1.1 1.125,1.4 1.475,1.4 1.475,1.1 1.125,1.1
  text "13" at -0.214,-0.158 h0.5
  text "12" at 1.087,1.089 h0.5
  text "7" at 1.196,-1.408 h0.5
  text "6" at -1.406,-1.408 h0.5
  text "'.Designator'" at -2,0 h0.75
  text "1" at -1.359,1.089 h0.5
M16-Top Courtyard:
  lines w0.01: -1.85,-1.75 1.85,-1.75 1.85,1.75 -1.85,1.75 -1.85,-1.75
3D body: height 0.05, standoff 0, extent -1.475,-0.9 -1.125,-0.598
3D body: height 0.05, standoff 0, extent -1.475,-1.4 -1.125,-1.098
3D body: height 0.05, standoff 0, extent -1.475,1.1 -1.125,1.402
3D body: height 0.05, standoff 0, extent 1.125,1.1 1.475,1.402
3D body: height 0.05, standoff 0, extent -0.725,-1.3 0.725,1.3
3D body: height 0.05, standoff 0, extent 1.125,-0.9 1.475,-0.598
3D body: height 0.05, standoff 0, extent 1.125,-0.4 1.475,-0.098
3D body: height 0.05, standoff 0, extent 1.125,0.1 1.475,0.402
3D body: height 0.05, standoff 0, extent 1.125,0.6 1.475,0.902
3D body: height 0.05, standoff 0, extent -1.475,0.6 -1.125,0.902
3D body: height 0.05, standoff 0, extent -1.475,0.1 -1.125,0.402
3D body: height 0.05, standoff 0, extent 1.125,-1.4 1.475,-1.098
3D body: height 0.05, standoff 0, extent -1.475,-0.4 -1.125,-0.098
3D body: height 0.6, standoff 0.05, extent -1.556,-1.55 1.55,1.554
3D body: height 0.61, standoff 0.6, extent -1.407,1.108 -1.107,1.408

## ICC_UFQFN16-EPAD_2P6X1P8_P040 [mm]
height 0.55
pads (17):
  rect 0.2x0.35 smd mask+0.05: 1(-0.6,-0.775) 2(-0.2,-0.775) 3(0.2,-0.775) 4(0.6,-0.775) 9(0.6,0.775) 10(0.2,0.775) 11(-0.2,0.775) 12(-0.6,0.775)
  rect 0.35x0.2 smd mask+0.05: 5(1.175,-0.6) 6(1.175,-0.2) 7(1.175,0.2) 8(1.175,0.6) 13(-1.175,0.6) 14(-1.175,0.2) 15(-1.175,-0.2) 16(-1.175,-0.6)
  rect 1.6x0.8 smd mask+0.05: 17(0,0)
Top Overlay:
  lines w0.12: -1.325,-0.825 -1.325,-0.925 -0.825,-0.925 ; -1.325,0.825 -1.325,0.925 -0.825,0.925 ; 0.825,-0.925 1.325,-0.925 1.325,-0.825 ; 0.825,0.925 1.325,0.925 1.325,0.825
  text "1" at -0.6,-1.3 h1.2
M14-Top Assembly:
  circle w0.01: c-0.825,-0.75 r0.106
  lines w0.01: -1.35,-0.7 -1.35,-0.5 -1.325,-0.5 -1.325,-0.7 -1.35,-0.7 ; -1.35,-0.3 -1.35,-0.1 -1.325,-0.1 -1.325,-0.3 -1.35,-0.3 ; -1.35,0.1 -1.35,0.3 -1.325,0.3 -1.325,0.1 -1.35,0.1 ; -1.35,0.5 -1.325,0.5 -1.325,0.7 -1.35,0.7 -1.35,0.5 ; -1.325,-0.925 -1.325,0.925 1.325,0.925 1.325,-0.925 -1.325,-0.925 ; -0.7,-0.95 -0.7,-0.925 -0.5,-0.925 -0.5,-0.95 -0.7,-0.95 ; -0.7,0.925 -0.7,0.95 -0.5,0.95 -0.5,0.925 -0.7,0.925 ; -0.3,-0.95 -0.3,-0.925 -0.1,-0.925 -0.1,-0.95 -0.3,-0.95 ; -0.3,0.925 -0.3,0.95 -0.1,0.95 -0.1,0.925 -0.3,0.925 ; 0.1,-0.95 0.1,-0.925 0.3,-0.925 0.3,-0.95 0.1,-0.95 ; 0.1,0.925 0.1,0.95 0.3,0.95 0.3,0.925 0.1,0.925 ; 0.5,-0.95 0.5,-0.925 0.7,-0.925 0.7,-0.95 0.5,-0.95 ; 0.5,0.925 0.5,0.95 0.7,0.95 0.7,0.925 0.5,0.925 ; 1.325,-0.7 1.35,-0.7 1.35,-0.5 1.325,-0.5 1.325,-0.7 ; 1.325,-0.3 1.35,-0.3 1.35,-0.1 1.325,-0.1 1.325,-0.3 ; 1.325,0.1 1.35,0.1 1.35,0.3 1.325,0.3 1.325,0.1 ; 1.325,0.5 1.35,0.5 1.35,0.7 1.325,0.7 1.325,0.5
  text "'.Designator'" at -2,-0.5 h0.75
  text "16" at -1.275,-0.7 h0.4
  text "13" at -1.275,0.475 h0.4
  text "12" at -0.775,0.625 h0.4
  text "9" at 0.525,0.625 h0.4
  text "8" at 1.1,0.475 h0.4
  text "5" at 1.1,-0.725 h0.4
  text "4" at 0.5,-0.875 h0.4
  text "1" at -0.65,-0.875 h0.4
M16-Top Courtyard:
  lines w0.01: -1.525,-1.125 -1.525,1.125 1.525,1.125 1.525,-1.125 -1.525,-1.125
3D body "QFN16_2P6X1P8_P040.STEP": height 0.55, standoff 0, extent -1.31,-0.91 1.31,0.91
3D body: height 0.55, standoff 0, extent -1.325,-0.925 1.325,0.925
3D body: height 0.56, standoff 0.55, extent -1.249,-0.85 -0.95,-0.55

## ICC_UFQFN16_2P6X1P8_P040 [mm] "MCD-03223"
height 0.6
pads (16):
  rect 0.2x0.45 smd mask+0.05: 1(-0.6,-0.725) 2(-0.2,-0.725) 3(0.2,-0.725) 4(0.6,-0.725) 9(0.6,0.725) 10(0.2,0.725) 11(-0.2,0.725) 12(-0.6,0.725)
  rect 0.45x0.2 smd mask+0.05: 5(1.125,-0.6) 6(1.125,-0.2) 7(1.125,0.2) 8(1.125,0.6) 13(-1.125,0.6) 14(-1.125,0.2) 15(-1.125,-0.2) 16(-1.125,-0.6)
Top Overlay:
  lines w0.12: -1.325,-0.825 -1.325,-0.925 -0.825,-0.925 ; -1.325,0.825 -1.325,0.925 -0.825,0.925 ; 0.825,-0.925 1.325,-0.925 1.325,-0.825 ; 0.825,0.925 1.325,0.925 1.325,0.825
  text "1" at -0.6,-1.3 h1.2
M14-Top Assembly:
  circle w0.01: c-0.825,-0.75 r0.106
  lines w0.01: -1.35,-0.7 -1.35,-0.5 -1.325,-0.5 -1.325,-0.7 -1.35,-0.7 ; -1.35,-0.3 -1.35,-0.1 -1.325,-0.1 -1.325,-0.3 -1.35,-0.3 ; -1.35,0.1 -1.35,0.3 -1.325,0.3 -1.325,0.1 -1.35,0.1 ; -1.35,0.5 -1.325,0.5 -1.325,0.7 -1.35,0.7 -1.35,0.5 ; -1.325,-0.925 -1.325,0.925 1.325,0.925 1.325,-0.925 -1.325,-0.925 ; -0.7,-0.95 -0.7,-0.925 -0.5,-0.925 -0.5,-0.95 -0.7,-0.95 ; -0.7,0.925 -0.7,0.95 -0.5,0.95 -0.5,0.925 -0.7,0.925 ; -0.3,-0.95 -0.3,-0.925 -0.1,-0.925 -0.1,-0.95 -0.3,-0.95 ; -0.3,0.925 -0.3,0.95 -0.1,0.95 -0.1,0.925 -0.3,0.925 ; 0.1,-0.95 0.1,-0.925 0.3,-0.925 0.3,-0.95 0.1,-0.95 ; 0.1,0.925 0.1,0.95 0.3,0.95 0.3,0.925 0.1,0.925 ; 0.5,-0.95 0.5,-0.925 0.7,-0.925 0.7,-0.95 0.5,-0.95 ; 0.5,0.925 0.5,0.95 0.7,0.95 0.7,0.925 0.5,0.925 ; 1.325,-0.7 1.35,-0.7 1.35,-0.5 1.325,-0.5 1.325,-0.7 ; 1.325,-0.3 1.35,-0.3 1.35,-0.1 1.325,-0.1 1.325,-0.3 ; 1.325,0.1 1.35,0.1 1.35,0.3 1.325,0.3 1.325,0.1 ; 1.325,0.5 1.35,0.5 1.35,0.7 1.325,0.7 1.325,0.5
  text "'.Designator'" at 0,0 h0.75
  text "16" at -1.275,-0.7 h0.4
  text "13" at -1.275,0.475 h0.4
  text "12" at -0.775,0.625 h0.4
  text "9" at 0.525,0.625 h0.4
  text "8" at 1.1,0.475 h0.4
  text "5" at 1.1,-0.725 h0.4
  text "4" at 0.5,-0.875 h0.4
  text "1" at -0.65,-0.875 h0.4
M16-Top Courtyard:
  lines w0.01: -1.525,-1.125 -1.525,1.125 1.525,1.125 1.525,-1.125 -1.525,-1.125
3D body: height 0.6, standoff 0, extent -1.325,-0.925 1.325,0.925
3D body: height 0.61, standoff 0.6, extent -1.249,-0.85 -0.95,-0.55

## ICC_UFQFPN20_3X3_P050 [mm] "MCD-02302"
height 0.6
pads (20):
  oct 0.525x0.3 smd mask+0.05: 1(-1.4,1) 5(-1.4,-1) 11(1.4,-1) 15(1.4,1)
  rrect25% 0.8x0.3 smd mask+0.05: 2(-1.35,0.5) 3(-1.35,0) 4(-1.35,-0.5) 12(1.35,-0.5) 13(1.35,0) 14(1.35,0.5)
  oct 0.3x0.525 smd mask+0.05: 6(-1,-1.4) 10(1,-1.4) 16(1,1.4) 20(-1,1.4)
  rrect25% 0.3x0.8 smd mask+0.05: 7(-0.5,-1.35) 8(0,-1.35) 9(0.5,-1.35) 17(0.5,1.35) 18(0,1.35) 19(-0.5,1.35)
Top Overlay:
  circle w0.12: c-0.925,0.925 r0.175
  lines w0.12: -1.775,1.275 -1.775,1.775 -1.275,1.775 ; -1.55,-1.275 -1.55,-1.55 -1.275,-1.55 ; -1.55,1.275 -1.55,1.55 -1.275,1.55 ; 1.27,-1.546 1.545,-1.546 1.545,-1.271 ; 1.27,1.554 1.545,1.554 1.545,1.279
M14-Top Assembly:
  circle w0.01: c-0.925,0.925 r0.202
  lines w0.01: -1.65,-1.147 -1.65,-0.847 -1.3,-0.847 -1.225,-0.922 -1.225,-1.072 -1.3,-1.147 -1.55,-1.147 -1.65,-1.147 ; -1.65,-0.647 -1.05,-0.647 -1.05,-0.347 -1.65,-0.347 -1.65,-0.647 ; -1.65,-0.147 -1.05,-0.147 -1.05,0.153 -1.65,0.153 -1.65,-0.147 ; -1.65,0.353 -1.05,0.353 -1.05,0.653 -1.65,0.653 -1.65,0.353 ; -1.65,0.853 -1.65,1.153 -1.3,1.153 -1.225,1.078 -1.225,0.928 -1.3,0.853 -1.55,0.853 -1.65,0.853 ; -1.55,-1.55 -1.55,1.55 1.55,1.55 1.55,-1.55 -1.55,-1.55 ; -1.15,-1.65 -1.15,-1.3 -1.075,-1.225 -0.925,-1.225 -0.85,-1.3 -0.85,-1.55 -0.85,-1.65 -1.15,-1.65 ; -1.15,1.3 -1.15,1.55 -1.15,1.65 -0.85,1.65 -0.85,1.3 -0.925,1.225 -1.075,1.225 -1.15,1.3 ; -0.65,-1.65 -0.65,-1.05 -0.35,-1.05 -0.35,-1.65 -0.65,-1.65 ; -0.65,1.05 -0.65,1.65 -0.35,1.65 -0.35,1.05 -0.65,1.05 ; -0.15,-1.65 -0.15,-1.05 0.15,-1.05 0.15,-1.65 -0.15,-1.65 ; -0.15,1.05 -0.15,1.65 0.15,1.65 0.15,1.05 -0.15,1.05 ; 0.35,-1.65 0.35,-1.05 0.65,-1.05 0.65,-1.65 0.35,-1.65 ; 0.35,1.05 0.35,1.65 0.65,1.65 0.65,1.05 0.35,1.05 ; 0.85,-1.65 0.85,-1.3 0.925,-1.225 1.075,-1.225 1.15,-1.3 1.15,-1.55 1.15,-1.65 0.85,-1.65 ; 0.85,1.3 0.85,1.55 0.85,1.65 1.15,1.65 1.15,1.3 1.075,1.225 0.925,1.225 0.85,1.3 ; 1.05,-0.647 1.05,-0.347 1.65,-0.347 1.65,-0.647 1.05,-0.647 ; 1.05,-0.147 1.05,0.153 1.65,0.153 1.65,-0.147 1.05,-0.147 ; 1.05,0.353 1.05,0.653 1.65,0.653 1.65,0.353 1.05,0.353 ; 1.225,-1.072 1.225,-0.922 1.3,-0.847 1.55,-0.847 1.65,-0.847 1.65,-1.147 1.3,-1.147 1.225,-1.072 ; 1.225,0.928 1.225,1.078 1.3,1.153 1.55,1.153 1.65,1.153 1.65,0.853 1.3,0.853 1.225,0.928
  text "20" at -1.225,1.2 h0.5
  text "16" at 0.775,1.2 h0.5
  text "15" at 1.1,0.85 h0.5
  text "11" at 1.15,-1.15 h0.5
  text "10" at 0.775,-1.519 h0.5
  text "6" at -1.1,-1.519 h0.5
  text "5" at -1.512,-1.144 h0.5
  text "1" at -1.493,0.85 h0.5
  text "'.Designator'" at -1.825,-0.3 h0.75
M16-Top Courtyard:
  lines w0.01: -1.9,-1.9 1.9,-1.9 1.9,1.9 -1.9,1.9 -1.9,-1.9
3D body "UFQFPN20-1.STEP": height 0.55, standoff 0, extent -1.5,-1.5 1.5,1.5

## ICC_UFQFPN28_4X4_P050 [mm] "MCD-02218"
height 0.6
pads (28):
  rect 0.3x0.3 smd mask+0.05: 1(-1.5,-2) 7(1.5,-2) 8(2,-1.5) 14(2,1.5) 15(1.5,2) 21(-1.5,2) 22(-2,1.5) 28(-2,-1.5)
  rect 0.3x0.55 smd mask+0.05: 2(-1,-1.875) 3(-0.5,-1.875) 4(0,-1.875) 5(0.5,-1.875) 6(1,-1.875) 16(1,1.875) 17(0.5,1.875) 18(0,1.875) 19(-0.5,1.875) 20(-1,1.875)
  rect 0.55x0.3 smd mask+0.05: 9(1.875,-1) 10(1.875,-0.5) 11(1.875,0) 12(1.875,0.5) 13(1.875,1) 23(-1.875,1) 24(-1.875,0.5) 25(-1.875,0) 26(-1.875,-0.5) 27(-1.875,-1)
Top Layer:
  region: 1.35,2.15 1.35,1.65 1.5,1.65 1.65,1.8 1.65,2.15
  region: 2.15,1.35 1.65,1.35 1.65,1.5 1.8,1.65 2.15,1.65
  region: 1.35,-2.15 1.35,-1.65 1.5,-1.65 1.65,-1.8 1.65,-2.15
  region: 2.15,-1.35 1.65,-1.35 1.65,-1.5 1.8,-1.65 2.15,-1.65
  region: -1.35,-2.15 -1.35,-1.65 -1.5,-1.65 -1.65,-1.8 -1.65,-2.15
  region: -2.15,-1.35 -1.65,-1.35 -1.65,-1.5 -1.8,-1.65 -2.15,-1.65
  region: -2.15,1.35 -1.65,1.35 -1.65,1.5 -1.8,1.65 -2.15,1.65
  region: -1.35,2.15 -1.35,1.65 -1.5,1.65 -1.65,1.8 -1.65,2.15
Top Overlay:
  circle w0.12: c-1.125,-1.15 r0.2
  lines w0.12: -2,-1.825 -2,-2 -1.825,-2 ; -2,1.825 -2,2 -1.825,2 ; 1.825,-2 2,-2 2,-1.825 ; 1.825,2 2,2 2,1.825
  text "1" at -1.275,-2.625 h1.5
M14-Top Assembly:
  circle w0.01: c-1.275,-1.325 r0.18
  lines w0.01: -2,-1.62 -1.65,-1.62 -1.65,-1.38 -2,-1.38 ; -2,-1.12 -1.6,-1.12 -1.6,-0.88 -2,-0.88 ; -2,-0.62 -1.6,-0.62 -1.6,-0.38 -2,-0.38 ; -2,-0.12 -1.6,-0.12 -1.6,0.12 -2,0.12 ; -2,0.38 -1.6,0.38 -1.6,0.62 -2,0.62 ; -2,0.88 -1.6,0.88 -1.6,1.12 -2,1.12 ; -2,1.38 -1.65,1.38 -1.65,1.62 -2,1.62 ; -1.62,-2 -1.62,-1.65 -1.38,-1.65 -1.38,-2 ; -1.62,2 -1.62,1.65 -1.38,1.65 -1.38,2 ; -1.12,-2 -1.12,-1.6 -0.88,-1.6 -0.88,-2 ; -1.12,2 -1.12,1.6 -0.88,1.6 -0.88,2 ; -0.62,-2 -0.62,-1.6 -0.38,-1.6 -0.38,-2 ; -0.62,2 -0.62,1.6 -0.38,1.6 -0.38,2 ; -0.12,-2 -0.12,-1.6 0.12,-1.6 0.12,-2 ; -0.12,2 -0.12,1.6 0.12,1.6 0.12,2 ; 0.38,-2 0.38,-1.6 0.62,-1.6 0.62,-2 ; 0.38,2 0.38,1.6 0.62,1.6 0.62,2 ; 0.88,-2 0.88,-1.6 1.12,-1.6 1.12,-2 ; 0.88,2 0.88,1.6 1.12,1.6 1.12,2 ; 1.38,-2 1.38,-1.65 1.62,-1.65 1.62,-2 ; 1.38,2 1.38,1.65 1.62,1.65 1.62,2 ; 2,-1.62 1.65,-1.62 1.65,-1.38 2,-1.38 ; 2,-1.12 1.6,-1.12 1.6,-0.88 2,-0.88 ; 2,-0.62 1.6,-0.62 1.6,-0.38 2,-0.38 ; 2,-0.12 1.6,-0.12 1.6,0.12 2,0.12 ; 2,0.38 1.6,0.38 1.6,0.62 2,0.62 ; 2,0.88 1.6,0.88 1.6,1.12 2,1.12 ; 2,1.38 1.65,1.38 1.65,1.62 2,1.62 ; -2,-2 2,-2 2,2 -2,2 -2,-2
  text "'.Designator'" at -2,-0.5 h0.75
  text "1" at -1.575,-1.975 h0.5
  text "7" at 1.4,-1.975 h0.5
  text "8" at 1.975,-1.6 h0.5
  text "14" at 1.95,1.275 h0.5
  text "15" at 1.275,1.65 h0.5
  text "21" at -1.725,1.675 h0.5
  text "22" at -1.975,1.7 h0.5
  text "28" at -1.975,-1.275 h0.5
M16-Top Courtyard:
  lines w0.01: -2.3,-2.3 -2.3,2.3 2.3,2.3 2.3,-2.3 -2.3,-2.3
3D body "User Library-UFQFPN28-1.STEP": height 0.55, standoff 0, extent -2,-2 2,2
3D body: height 0.6, standoff 0, extent -2,-2 2,2

## ICC_UFQFPN32-EPAD_5X5_P050 [mm] "MCD-01398"
height 1
pads (33):
  oval 0.3x0.75 smd mask+0.05: 1(-1.75,-2.425) 2(-1.25,-2.425) 3(-0.75,-2.425) 4(-0.25,-2.425) 5(0.25,-2.425) 6(0.75,-2.425) 7(1.25,-2.425) 8(1.75,-2.425) 17(1.75,2.425) 18(1.25,2.425) 19(0.75,2.425) 20(0.25,2.425) 21(-0.25,2.425) 22(-0.75,2.425) 23(-1.25,2.425) 24(-1.75,2.425)
  oval 0.75x0.3 smd mask+0.05: 9(2.425,-1.75) 10(2.425,-1.25) 11(2.425,-0.75) 12(2.425,-0.25) 13(2.425,0.25) 14(2.425,0.75) 15(2.425,1.25) 16(2.425,1.75) 25(-2.425,1.75) 26(-2.425,1.25) 27(-2.425,0.75) 28(-2.425,0.25) 29(-2.425,-0.25) 30(-2.425,-0.75) 31(-2.425,-1.25) 32(-2.425,-1.75)
  rect 3.7x3.7 smd mask+0.05: 33(0,0)
Top Overlay:
  circle w0.12: c-2.3,-2.3 r0.2
  lines w0.12: -2.625,-2.05 -2.625,-2.625 -2.05,-2.625 ; -2.625,2.05 -2.625,2.625 -2.05,2.625 ; 2.05,-2.625 2.625,-2.625 2.625,-2.05 ; 2.05,2.625 2.625,2.625 2.625,2.05
  text "1" at -2,-3.075 h1.5
M14-Top Assembly:
  circle w0.01: c-2.125,-2.25 r0.18
  lines w0.01: -2.55,-1.87 -2.1,-1.87 -2.1,-1.63 -2.55,-1.63 ; -2.55,-1.37 -2.1,-1.37 -2.1,-1.13 -2.55,-1.13 ; -2.55,-0.87 -2.1,-0.87 -2.1,-0.63 -2.55,-0.63 ; -2.55,-0.37 -2.1,-0.37 -2.1,-0.13 -2.55,-0.13 ; -2.55,0.13 -2.1,0.13 -2.1,0.37 -2.55,0.37 ; -2.55,0.63 -2.1,0.63 -2.1,0.87 -2.55,0.87 ; -2.55,1.13 -2.1,1.13 -2.1,1.37 -2.55,1.37 ; -2.55,1.63 -2.1,1.63 -2.1,1.87 -2.55,1.87 ; -1.87,-2.55 -1.87,-2.1 -1.63,-2.1 -1.63,-2.55 ; -1.87,2.55 -1.87,2.1 -1.63,2.1 -1.63,2.55 ; -1.37,-2.55 -1.37,-2.1 -1.13,-2.1 -1.13,-2.55 ; -1.37,2.55 -1.37,2.1 -1.13,2.1 -1.13,2.55 ; -0.87,-2.55 -0.87,-2.1 -0.63,-2.1 -0.63,-2.55 ; -0.87,2.55 -0.87,2.1 -0.63,2.1 -0.63,2.55 ; -0.37,-2.55 -0.37,-2.1 -0.13,-2.1 -0.13,-2.55 ; -0.37,2.55 -0.37,2.1 -0.13,2.1 -0.13,2.55 ; 0.13,-2.55 0.13,-2.1 0.37,-2.1 0.37,-2.55 ; 0.13,2.55 0.13,2.1 0.37,2.1 0.37,2.55 ; 0.63,-2.55 0.63,-2.1 0.87,-2.1 0.87,-2.55 ; 0.63,2.55 0.63,2.1 0.87,2.1 0.87,2.55 ; 1.13,-2.55 1.13,-2.1 1.37,-2.1 1.37,-2.55 ; 1.13,2.55 1.13,2.1 1.37,2.1 1.37,2.55 ; 1.63,-2.55 1.63,-2.1 1.87,-2.1 1.87,-2.55 ; 1.63,2.55 1.63,2.1 1.87,2.1 1.87,2.55 ; 2.55,-1.87 2.1,-1.87 2.1,-1.63 2.55,-1.63 ; 2.55,-1.37 2.1,-1.37 2.1,-1.13 2.55,-1.13 ; 2.55,-0.87 2.1,-0.87 2.1,-0.63 2.55,-0.63 ; 2.55,-0.37 2.1,-0.37 2.1,-0.13 2.55,-0.13 ; 2.55,0.13 2.1,0.13 2.1,0.37 2.55,0.37 ; 2.55,0.63 2.1,0.63 2.1,0.87 2.55,0.87 ; 2.55,1.13 2.1,1.13 2.1,1.37 2.55,1.37 ; 2.55,1.63 2.1,1.63 2.1,1.87 2.55,1.87 ; -2.55,-2.55 2.55,-2.55 2.55,2.55 -2.55,2.55 -2.55,-2.55 ; -1.8,-1.787 1.807,-1.787 1.807,1.82 -1.8,1.82 -1.8,-1.787
  text "'.Designator'" at -2,0.25 h0.75
  text "1" at -1.8,-2.475 h0.5
  text "8" at 1.65,-2.475 h0.5
  text "9" at 2.45,-1.85 h0.5
  text "16" at 2.45,1.575 h0.5
  text "17" at 1.55,2.15 h0.5
  text "24" at -1.975,2.175 h0.5
  text "25" at -2.45,2 h0.5
  text "32" at -2.45,-1.525 h0.5
  text "33" at -0.275,-0.15 h0.5
M16-Top Courtyard:
  lines w0.01: -2.95,-2.95 -2.95,2.95 2.95,2.95 2.95,-2.95 -2.95,-2.95
3D body "UFQFPN-32.STEP": height 0.55, standoff 0, extent -2.5,-2.5 2.5,2.5
3D body: height 0.6, standoff 0, extent -2.55,-2.55 2.55,2.55

## ICC_UFQFPN48-EPAD_7X7_H0P55_P050 [mm] "MCD-01704"
height 0.65
pads (49):
  rect 0.55x0.3 smd mask+0.05: 1(-3.375,2.75) 2(-3.375,2.25) 3(-3.375,1.75) 4(-3.375,1.25) 5(-3.375,0.75) 6(-3.375,0.25) 7(-3.375,-0.25) 8(-3.375,-0.75) 9(-3.375,-1.25) 10(-3.375,-1.75) 11(-3.375,-2.25) 12(-3.375,-2.75) 25(3.375,-2.75) 26(3.375,-2.25) 27(3.375,-1.75) 28(3.375,-1.25) 29(3.375,-0.75) 30(3.375,-0.25) 31(3.375,0.25) 32(3.375,0.75) 33(3.375,1.25) 34(3.375,1.75) 35(3.375,2.25) 36(3.375,2.75)
  rect 0.3x0.55 smd mask+0.05: 13(-2.75,-3.375) 14(-2.25,-3.375) 15(-1.75,-3.375) 16(-1.25,-3.375) 17(-0.75,-3.375) 18(-0.25,-3.375) 19(0.25,-3.375) 20(0.75,-3.375) 21(1.25,-3.375) 22(1.75,-3.375) 23(2.25,-3.375) 24(2.75,-3.375) 37(2.75,3.375) 38(2.25,3.375) 39(1.75,3.375) 40(1.25,3.375) 41(0.75,3.375) 42(0.25,3.375) 43(-0.25,3.375) 44(-0.75,3.375) 45(-1.25,3.375) 46(-1.75,3.375) 47(-2.25,3.375) 48(-2.75,3.375)
  rect 5.6x5.6 smd mask+0.05: 49(0,0)
Top Overlay:
  lines w0.12: -3.55,-3.025 -3.55,-3.55 -3.025,-3.55 ; -3.55,3.025 -3.55,3.55 -3.025,3.55 ; 3.025,-3.55 3.55,-3.55 3.55,-3.025 ; 3.025,3.55 3.55,3.55 3.55,3.025 ; -3.4,3.1 -3.1,3.1 -3.1,3.4 -3.4,3.4 -3.4,3.1
  text "1" at -4.1,2.25 h1.5
M14-Top Assembly:
  drawing of 156 lines, arcs and shapes, not listed
  text "1" at -3.425,2.6 h0.5
  text "'.Designator'" at -2,0.8 h0.75
  text "48" at -3,3.2 h0.5
  text "12" at -3.525,-2.9 h0.5
  text "13" at -2.975,-3.5 h0.5
  text "24" at 2.525,-3.5 h0.5
  text "25" at 3.05,-2.9 h0.5
  text "36" at 3.05,2.6 h0.5
  text "37" at 2.525,3.2 h0.5
  text "49" at -0.25,-0.15 h0.5
M16-Top Courtyard:
  lines w0.01: -3.8,-3.8 -3.8,3.8 3.8,3.8 3.8,-3.8 -3.8,-3.8
3D body "UFQFPN48.STEP": height 0.55, standoff 0, extent -3.5,-3.5 3.5,3.5
3D body: height 0.65, standoff 0, extent -3.5,-3.5 3.5,3.5

## ICC_UQFN10_RSE_R-PUQFN-N10_1P5X2_P050 [mm] "MCD-01847"
height 0.6
pads (10):
  rect 0.6x0.35 smd mask+0.05: 1(-0.7,0.75) 4(-0.7,-0.75) 6(0.7,-0.75) 9(0.7,0.75)
  rect 0.6x0.25 smd mask+0.05: 2(-0.7,0.25) 3(-0.7,-0.25) 7(0.7,-0.25) 8(0.7,0.25)
  rect 0.4x0.9 smd mask+0.05: 5(0,-0.85) 10(0,0.85)
Top Overlay:
  lines w0.12: -0.75,-1.05 -0.325,-1.05 ; -0.75,1.05 -0.325,1.05 ; 0.325,-1.05 0.75,-1.05 ; 0.325,1.05 0.75,1.05
  text "1" at -1.125,1.475 h1.3
M14-Top Assembly:
  lines w0.01: -0.75,-0.9 -0.4,-0.9 -0.4,-0.6 -0.75,-0.6 ; -0.75,-0.375 -0.4,-0.375 -0.4,-0.125 -0.75,-0.125 ; -0.75,0.125 -0.4,0.125 -0.4,0.375 -0.75,0.375 ; -0.75,0.6 -0.4,0.6 -0.4,0.9 -0.75,0.9 ; -0.175,-1 -0.175,-0.55 0.175,-0.55 0.175,-1 ; -0.175,1 -0.175,0.55 0.175,0.55 0.175,1 ; 0.75,-0.9 0.4,-0.9 0.4,-0.6 0.75,-0.6 ; 0.75,-0.375 0.4,-0.375 0.4,-0.125 0.75,-0.125 ; 0.75,0.125 0.4,0.125 0.4,0.375 0.75,0.375 ; 0.75,0.6 0.4,0.6 0.4,0.9 0.75,0.9 ; -0.75,-1 -0.75,1 0.75,1 0.75,-1 -0.75,-1
  text "5" at -0.1,-0.95 h0.5
  text "10" at -0.2,0.65 h0.5
  text "9" at 0.425,0.875 h0.5
  text "6" at 0.425,-0.65 h0.5
  text "4" at -0.75,-0.65 h0.5
  text "1" at -0.75,0.825 h0.5
  text "'.Designator'" at -2,-0.5 h0.75
M16-Top Courtyard:
  lines w0.01: -1.15,-1.45 1.15,-1.45 1.15,1.45 -1.15,1.45 -1.15,-1.45
3D body: height 0.6, standoff 0, extent -0.75,-1 0.75,1
3D body "QFN-10 2x1_5mm.STEP": height 0.6, standoff 0, extent -0.75,-1 0.75,1

## ICC_UQFN10_RSW_R-PUQFN-N10_1P8X1P4_P040 [mm] "MCD-01829"
height 0.55
pads (10):
  rect 0.2x0.9 smd mask+0.05: 1(-0.2,-0.65)
  rect 0.2x0.8 smd mask+0.05: 2(0.2,-0.7) 6(0.2,0.7) 7(-0.2,0.7)
  rect 0.8x0.2 smd mask+0.05: 3(0.9,-0.4) 4(0.9,0) 5(0.9,0.4) 8(-0.9,0.4) 9(-0.9,0) 10(-0.9,-0.4)
Top Overlay:
  lines w0.12: -0.95,-0.625 -0.95,-0.75 -0.425,-0.75 ; -0.95,0.625 -0.95,0.75 -0.425,0.75 ; 0.425,-0.75 0.95,-0.75 0.95,-0.675 ; 0.425,0.75 0.95,0.75 0.95,0.625
  text "1" at -0.4,-1.175 h1.3
M14-Top Assembly:
  lines w0.01: -0.95,-0.5 -0.5,-0.5 -0.5,-0.3 -0.95,-0.3 ; -0.95,-0.1 -0.5,-0.1 -0.5,0.1 -0.95,0.1 ; -0.95,0.3 -0.5,0.3 -0.5,0.5 -0.95,0.5 ; -0.3,-0.75 -0.3,-0.275 -0.225,-0.2 ; -0.3,0.75 -0.3,0.3 -0.1,0.3 -0.1,0.75 ; -0.1,-0.75 -0.1,-0.2 -0.225,-0.2 ; 0.1,-0.75 0.1,-0.3 0.3,-0.3 0.3,-0.75 ; 0.1,0.75 0.1,0.3 0.3,0.3 0.3,0.75 ; 0.95,-0.5 0.5,-0.5 0.5,-0.3 0.95,-0.3 ; 0.95,-0.1 0.5,-0.1 0.5,0.1 0.95,0.1 ; 0.95,0.3 0.5,0.3 0.5,0.5 0.95,0.5 ; -0.225,-0.2 -0.225,-0.2 ; -0.95,-0.75 0.95,-0.75 0.95,0.75 -0.95,0.75 -0.95,-0.75
  text "'.Designator'" at -2,-0.5 h0.75
  text "3" at 0.825,-0.463 h0.3
  text "4" at 0.825,-0.063 h0.3
  text "5" at 0.825,0.337 h0.3
  text "6" at 0.138,0.437 h0.3
  text "7" at -0.262,0.437 h0.3
  text "8" at -0.825,0.462 h0.3
  text "9" at -0.825,0.062 h0.3
  text "10" at -0.825,-0.275 h0.3
  text "1" at -0.238,-0.625 h0.3
  text "2" at 0.138,-0.625 h0.3
M16-Top Courtyard:
  lines w0.01: -1.45,-1.25 1.45,-1.25 1.45,1.25 -1.45,1.25 -1.45,-1.25
3D body: height 0.56, standoff 0.55, extent -0.329,-0.705 -0.07,-0.445
3D body: height 0.55, standoff 0, extent -0.95,-0.75 0.95,0.75
3D body "qfn10_rm0_4-1.STEP": height 0.55, standoff -0.01, extent -0.925,-0.725 0.925,0.725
